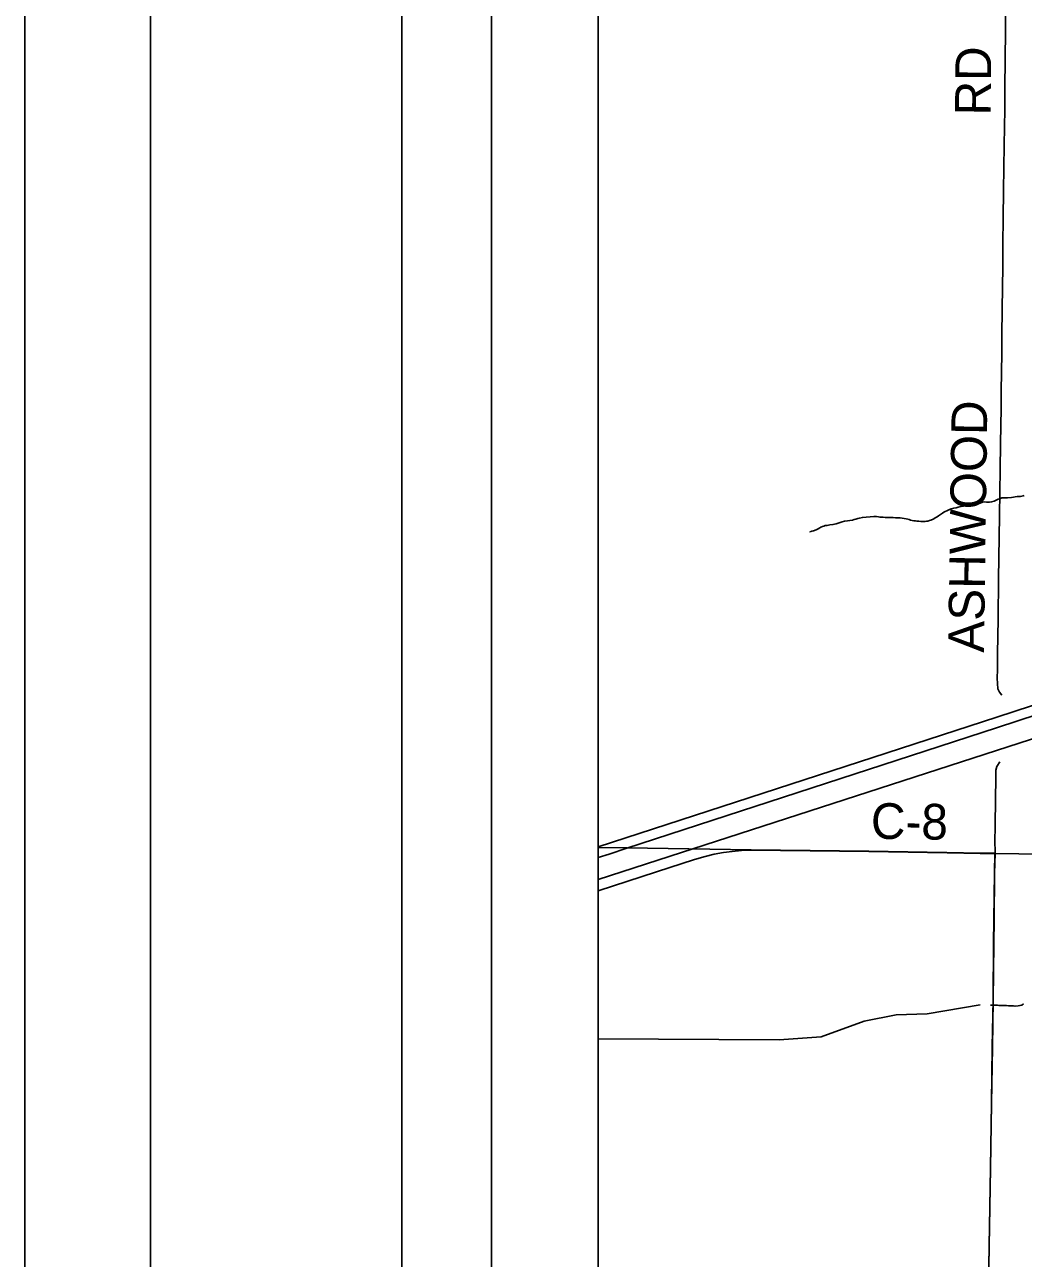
# Model space of a CAD drawing. Extents: x -483 to 680, y 0 to 440.
# Drawn here: x 0 to 79.4, y 248.8 to 346.9 of the extents above; entities that cross this region are included whole.
import ezdxf

# ---------------------------------------------------------------- set-up
doc = ezdxf.new("R2010")
doc.units = 0
for name, color, linetype in [('GM_X_County_Road', 7, 'Continuous'), ('GM_X_County_Road_Text', 7, 'Continuous'), ('GM_X_Minor_River', 7, 'Continuous'), ('GM_X_Rail_Line', 7, 'Continuous'), ('GM_X_Township_Road', 7, 'Continuous'), ('GM_X_Township_Road_Text', 7, 'Continuous'), ('GM_X_US_Route', 7, 'Continuous'), ('SH_Border', 7, 'Continuous'), ('SH_Cut_Line', 7, 'Continuous'), ('SH_Text', 7, 'Continuous')]:
    doc.layers.add(name, color=color, linetype=linetype)

msp = doc.modelspace()

# ---------------------------------------------------------------- linework, layer by layer
at = {"layer": 'GM_X_County_Road'}
for points in [[(57.77, 281.265), (64.794, 281.198), (67.126, 281.161), (73.344, 281.058), (75.987, 281.015), (77.163, 281.006)], [(77.163, 281.006), (79.053, 280.972), (84.585, 280.875), (89.278, 280.783), (90.894, 280.761), (92.697, 280.726), (94.033, 280.704), (94.748, 280.692), (95.649, 280.674), (99.658, 280.588), (101.585, 280.553), (106.278, 280.468), (107.954, 280.425), (111.436, 280.37), (117.186, 280.256), (121.537, 280.166), (124.893, 280.092), (126.566, 280.056)]]:
    msp.add_lwpolyline(points, dxfattribs=at)
at = {"layer": 'GM_X_Minor_River'}
for points in [[(79.481, 309.481), (79.386, 309.465), (79.194, 309.413), (78.909, 309.401), (78.471, 309.336), (78.147, 309.306), (78.033, 309.309), (77.919, 309.312), (77.824, 309.295), (77.71, 309.298), (77.595, 309.244), (77.404, 309.192), (77.288, 309.138), (77.096, 309.029), (76.885, 308.977), (76.714, 308.944), (76.6, 308.947), (76.486, 308.95), (76.354, 308.972), (76.163, 308.958), (75.971, 308.887), (75.819, 308.853), (75.647, 308.838), (75.495, 308.823), (75.361, 308.788), (75.209, 308.773), (75.076, 308.757), (74.98, 308.722), (74.884, 308.705)], [(74.884, 308.705), (74.77, 308.689), (74.617, 308.636), (74.464, 308.621), (74.331, 308.586), (74.216, 308.57), (74.063, 308.517), (73.872, 308.484), (73.681, 308.432), (73.527, 308.36), (73.316, 308.27), (73.182, 308.217), (73.086, 308.162), (72.969, 308.07), (72.66, 307.869), (72.545, 307.796), (72.448, 307.742), (72.236, 307.595), (72.063, 307.524), (71.948, 307.488), (71.814, 307.454), (71.719, 307.437), (71.604, 307.421), (71.491, 307.424), (71.396, 307.426), (71.263, 307.43), (71.092, 307.434), (70.94, 307.438), (70.827, 307.46), (70.713, 307.482), (70.562, 307.505), (70.449, 307.527), (70.336, 307.567), (70.223, 307.608), (70.09, 307.631), (69.92, 307.654), (69.768, 307.677), (69.617, 307.7), (69.446, 307.704), (69.238, 307.709), (69.048, 307.733), (68.839, 307.738), (68.63, 307.725), (68.421, 307.73), (68.251, 307.753), (68.118, 307.757), (68.004, 307.759), (67.891, 307.781), (67.74, 307.804), (67.512, 307.81), (67.226, 307.779), (66.903, 307.768), (66.617, 307.738), (66.369, 307.687), (66.254, 307.652), (66.082, 307.599), (65.967, 307.564), (65.833, 307.53), (65.624, 307.497), (65.414, 307.464), (65.185, 307.432), (65.013, 307.399), (64.515, 307.221), (64.267, 307.171), (64.019, 307.139), (63.81, 307.106), (63.657, 307.091), (63.542, 307.056), (63.427, 307.021), (63.312, 306.967), (63.216, 306.912), (63.1, 306.839), (62.946, 306.748), (62.716, 306.678), (62.582, 306.644), (62.467, 306.589), (62.448, 306.59), (62.467, 306.589)], [(45.608, 266.277), (59.988, 266.192), (63.334, 266.43), (66.759, 267.675), (69.308, 268.181), (71.761, 268.25), (75.987, 268.976)], [(76.805, 268.937), (77.138, 268.938), (77.252, 268.935), (77.347, 268.933), (77.461, 268.93), (77.556, 268.928), (77.689, 268.924), (77.822, 268.921), (77.955, 268.917), (78.069, 268.915), (78.22, 268.892), (78.372, 268.888), (78.524, 268.884), (78.638, 268.881), (78.751, 268.859), (78.999, 268.891), (79.132, 268.907), (79.285, 268.941), (79.42, 269.051)]]:
    msp.add_lwpolyline(points, dxfattribs=at)
at = {"layer": 'GM_X_Rail_Line'}
msp.add_line((45.608, 278.929), (52.231, 281.076), dxfattribs=at)
msp.add_lwpolyline([(52.231, 281.076), (127.278, 305.392), (222.338, 336.549), (257.887, 348.093), (262.457, 349.692), (266.922, 351.391), (271.85, 353.786), (276.063, 355.851), (279.587, 357.722), (282.074, 359.273), (284.73, 360.909), (286.844, 362.348), (291.566, 365.767), (297.907, 370.986), (306.481, 378.212), (309.709, 381.296), (311.628, 383.535), (313.46, 385.542), (315.408, 389.44), (316.608, 391.805), (318.711, 395.95)], dxfattribs=at)
at = {"layer": 'GM_X_Township_Road'}
for points in [[(77.701, 293.616), (77.501, 293.833), (77.367, 294.1), (77.339, 294.961), (77.347, 295.644), (77.365, 296.888), (77.4, 299.686), (77.44, 302.856), (77.517, 307.862), (77.552, 309.789), (77.572, 311.53), (77.601, 313.612), (77.634, 316.441), (77.652, 317.778), (77.677, 319.301), (77.695, 320.794), (77.708, 322.193), (77.733, 324.338), (77.771, 327.695), (77.784, 329.467), (77.812, 331.549), (77.841, 333.757), (77.887, 337.363), (77.927, 340.223), (77.941, 341.933), (77.96, 344.14), (77.993, 346.503), (78.024, 349.208)], [(77.163, 281.006), (77.153, 282.123), (77.17, 283.025), (77.207, 285.543), (77.224, 286.786), (77.233, 287.625), (77.301, 287.938), (77.551, 288.288)], [(45.608, 278.042), (50.247, 279.553), (53.264, 280.534), (54.102, 280.774), (54.83, 280.95), (55.565, 281.088), (56.245, 281.179), (56.991, 281.241), (57.77, 281.265)], [(57.77, 281.265), (64.794, 281.198), (67.126, 281.161), (73.344, 281.058), (75.987, 281.015), (77.163, 281.006)], [(76.405, 228.209), (76.41, 228.65), (76.418, 229.582), (76.442, 231.446), (76.566, 240.61), (76.648, 246.512), (76.701, 249.773), (76.803, 255.986), (76.879, 261.111), (76.953, 265.615), (77.008, 269.343), (77.055, 273.847), (77.077, 275.711), (77.117, 279.438), (77.163, 281.006)]]:
    msp.add_lwpolyline(points, dxfattribs=at)
at = {"layer": 'GM_X_US_Route'}
for p, q in [((45.608, 281.531), (77.288, 291.856)), ((47.885, 281.426), (77.267, 290.998))]:
    msp.add_line(p, q, dxfattribs=at)
for points in [[(77.288, 291.856), (122.784, 306.734), (124.838, 307.43), (126.301, 307.972), (127.421, 308.449)], [(77.267, 290.998), (123.029, 305.999), (125.191, 306.715), (126.663, 307.257), (127.389, 307.543)], [(45.608, 280.683), (46.477, 280.967), (47.885, 281.426)]]:
    msp.add_lwpolyline(points, dxfattribs=at)
at = {"layer": 'SH_Border'}
for points in [[(10, 430), (30, 430), (30, 10), (10, 10)], [(30, 430), (670, 430), (670, 10), (30, 10)]]:
    msp.add_lwpolyline(points, close=True, dxfattribs=at)
at = {"layer": 'SH_Cut_Line'}
msp.add_lwpolyline([(0, 0), (680, 0), (680, 440), (0, 440)], close=True, dxfattribs=at)
for points in [[(385.608, 55.95), (385.608, 395.95), (45.608, 395.95), (45.608, 281.486), (47.873, 281.454), (57.759, 281.293), (64.783, 281.226), (67.114, 281.188), (73.333, 281.086), (75.975, 281.043), (77.151, 281.034), (77.105, 279.466), (77.065, 275.738), (77.043, 273.874), (76.996, 269.37), (76.941, 265.642), (76.868, 261.138), (76.791, 256.013), (76.689, 249.801), (76.636, 246.539)], [(76.636, 246.539), (76.689, 249.801), (76.791, 256.013), (76.868, 261.138), (76.941, 265.642), (76.996, 269.37), (77.043, 273.874), (77.065, 275.738), (77.105, 279.466), (77.151, 281.034), (75.975, 281.043), (73.333, 281.086), (67.114, 281.188), (64.783, 281.226), (57.759, 281.293), (47.873, 281.454), (45.608, 281.486), (45.608, 55.95)]]:
    msp.add_lwpolyline(points, dxfattribs=at)
at = {"layer": 'SH_Text'}
for points in [[(37.108, 404.45), (394.108, 404.45), (394.108, 47.45), (37.108, 47.45)], [(45.608, 395.95), (385.608, 395.95), (385.608, 55.95), (45.608, 55.95)]]:
    msp.add_lwpolyline(points, close=True, dxfattribs=at)

# ---------------------------------------------------------------- texts
at = {"layer": 'GM_X_County_Road_Text'}
msp.add_text('C-8', height=2.8409, rotation=359.21439, dxfattribs=at).set_placement((67.273, 282.185))
at = {"layer": 'GM_X_Township_Road_Text'}
for s, rotation, p in [('RD', 89.5107, (76.815, 339.707)), ('ASHWOOD', 89.19105, (76.273, 296.977))]:
    msp.add_text(s, height=2.8409, rotation=rotation, dxfattribs=at).set_placement(p)

doc.saveas('drawing.dxf')
